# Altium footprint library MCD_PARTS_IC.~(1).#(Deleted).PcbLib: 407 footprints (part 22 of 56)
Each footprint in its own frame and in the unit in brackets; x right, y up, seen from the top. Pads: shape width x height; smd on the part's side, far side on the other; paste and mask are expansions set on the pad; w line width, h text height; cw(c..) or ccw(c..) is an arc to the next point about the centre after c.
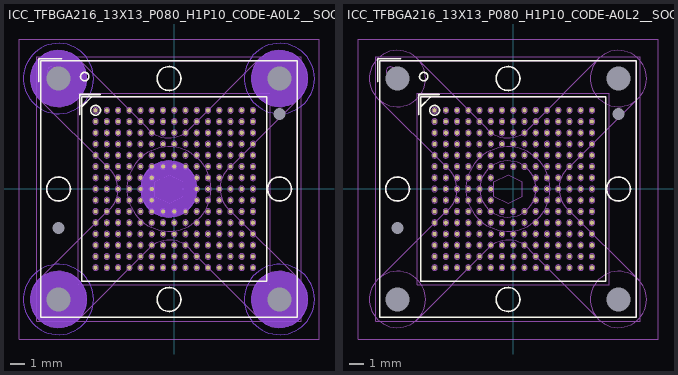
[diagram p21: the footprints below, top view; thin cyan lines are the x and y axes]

## ICC_TFBGA216_13X13_P080_H1P10_CODE-A0L2__SOCKET_IRONWOOD_CS1222291-D6524MF [mm] "MCD-02209"
height 8.25
pads (222):
  round 0.3 smd mask+0.05: A1(-5.6,5.6) A2(-4.8,5.6) A3(-4,5.6) A4(-3.2,5.6) A5(-2.4,5.6) A6(-1.6,5.6) A7(-0.8,5.6) A8(0,5.6) A9(0.8,5.6) A10(1.6,5.6) A11(2.4,5.6) A12(3.2,5.6) A13(4,5.6) A14(4.8,5.6) A15(5.6,5.6) B1(-5.6,4.8) B2(-4.8,4.8) B3(-4,4.8) B4(-3.2,4.8) B5(-2.4,4.8) B6(-1.6,4.8) B7(-0.8,4.8) B8(0,4.8) B9(0.8,4.8) B10(1.6,4.8) B11(2.4,4.8) B12(3.2,4.8) B13(4,4.8) B14(4.8,4.8) B15(5.6,4.8) C1(-5.6,4) C2(-4.8,4) C3(-4,4) C4(-3.2,4) C5(-2.4,4) C6(-1.6,4) C7(-0.8,4) C8(0,4) C9(0.8,4) C10(1.6,4) C11(2.4,4) C12(3.2,4) C13(4,4) C14(4.8,4) C15(5.6,4) D1(-5.6,3.2) D2(-4.8,3.2) D3(-4,3.2) D4(-3.2,3.2) D5(-2.4,3.2) D6(-1.6,3.2) D7(-0.8,3.2) D8(0,3.2) D9(0.8,3.2) D10(1.6,3.2) D11(2.4,3.2) D12(3.2,3.2) D13(4,3.2) D14(4.8,3.2) D15(5.6,3.2) E1(-5.6,2.4) E2(-4.8,2.4) E3(-4,2.4) E4(-3.2,2.4) E5(-2.4,2.4) E6(-1.6,2.4) E7(-0.8,2.4) E8(0,2.4) E9(0.8,2.4) E10(1.6,2.4) E11(2.4,2.4) E12(3.2,2.4) E13(4,2.4) E14(4.8,2.4) E15(5.6,2.4) F1(-5.6,1.6) F2(-4.8,1.6) F3(-4,1.6) F4(-3.2,1.6) F5(-2.4,1.6) F6(-1.6,1.6) F7(-0.8,1.6) F8(0,1.6) F9(0.8,1.6) F10(1.6,1.6) F11(2.4,1.6) F12(3.2,1.6) F13(4,1.6) F14(4.8,1.6) F15(5.6,1.6) G1(-5.6,0.8) G2(-4.8,0.8) G3(-4,0.8) G4(-3.2,0.8) G5(-2.4,0.8) G6(-1.6,0.8) G10(1.6,0.8) G11(2.4,0.8) G12(3.2,0.8) G13(4,0.8) G14(4.8,0.8) G15(5.6,0.8) H1(-5.6,0) H2(-4.8,0) H3(-4,0) H4(-3.2,0) H5(-2.4,0) H6(-1.6,0) H10(1.6,0) H11(2.4,0) H12(3.2,0) H13(4,0) H14(4.8,0) H15(5.6,0) J1(-5.6,-0.8) J2(-4.8,-0.8) J3(-4,-0.8) J4(-3.2,-0.8) J5(-2.4,-0.8) J6(-1.6,-0.8) J10(1.6,-0.8) J11(2.4,-0.8) J12(3.2,-0.8) J13(4,-0.8) J14(4.8,-0.8) J15(5.6,-0.8) K1(-5.6,-1.6) K2(-4.8,-1.6) K3(-4,-1.6) K4(-3.2,-1.6) K5(-2.4,-1.6) K6(-1.6,-1.6) K7(-0.8,-1.6) K8(0,-1.6) K9(0.8,-1.6) K10(1.6,-1.6) K11(2.4,-1.6) K12(3.2,-1.6) K13(4,-1.6) K14(4.8,-1.6) K15(5.6,-1.6) L1(-5.6,-2.4) L2(-4.8,-2.4) L3(-4,-2.4) L4(-3.2,-2.4) L5(-2.4,-2.4) L6(-1.6,-2.4) L7(-0.8,-2.4) L8(0,-2.4) L9(0.8,-2.4) L10(1.6,-2.4) L11(2.4,-2.4) L12(3.2,-2.4) L13(4,-2.4) L14(4.8,-2.4) L15(5.6,-2.4) M1(-5.6,-3.2) M2(-4.8,-3.2) M3(-4,-3.2) M4(-3.2,-3.2) M5(-2.4,-3.2) M6(-1.6,-3.2) M7(-0.8,-3.2) M8(0,-3.2) M9(0.8,-3.2) M10(1.6,-3.2) M11(2.4,-3.2) M12(3.2,-3.2) M13(4,-3.2) M14(4.8,-3.2) M15(5.6,-3.2) N1(-5.6,-4) N2(-4.8,-4) N3(-4,-4) N4(-3.2,-4) N5(-2.4,-4) N6(-1.6,-4) N7(-0.8,-4) N8(0,-4) N9(0.8,-4) N10(1.6,-4) N11(2.4,-4) N12(3.2,-4) N13(4,-4) N14(4.8,-4) N15(5.6,-4) P1(-5.6,-4.8) P2(-4.8,-4.8) P3(-4,-4.8) P4(-3.2,-4.8) P5(-2.4,-4.8) P6(-1.6,-4.8) P7(-0.8,-4.8) P8(0,-4.8) P9(0.8,-4.8) P10(1.6,-4.8) P11(2.4,-4.8) P12(3.2,-4.8) P13(4,-4.8) P14(4.8,-4.8) P15(5.6,-4.8) R1(-5.6,-5.6) R2(-4.8,-5.6) R3(-4,-5.6) R4(-3.2,-5.6) R5(-2.4,-5.6) R6(-1.6,-5.6) R7(-0.8,-5.6) R8(0,-5.6) R9(0.8,-5.6) R10(1.6,-5.6) R11(2.4,-5.6) R12(3.2,-5.6) R13(4,-5.6) R14(4.8,-5.6) R15(5.6,-5.6)
  round 0 hole 0.85 unplated mask+0.05: NPTH1(7.487,5.322) NPTH2(-8.238,-2.783)
  round 0 hole 1.71 unplated mask+0.05: PTH1(-8.238,7.862) PTH2(7.487,7.862) PTH3(7.487,-7.863) PTH4(-8.238,-7.863)
Bottom Layer keep-out:
  circle w0.01: c7.487,-7.863 r2.5
  circle w0.01: c-8.238,-7.863 r2.5
  circle w0.01: c-8.238,7.862 r2.5
  circle w0.01: c7.487,7.862 r2.5
  region: 1.6,-0.025 1.6,-0.221 1.524,-0.605 1.374,-0.966 1.156,-1.292 0.879,-1.569 0.554,-1.786 0.192,-1.936 -0.192,-2.012 -0.388,-2.012 -0.585,-2.012 -0.971,-1.936 -1.335,-1.785 -1.662,-1.566 -1.941,-1.287 -2.16,-0.96 -2.311,-0.596 -2.388,-0.209 -2.388,-0.012 -2.388,0.013 -2.388,0.209 -2.311,0.596 -2.16,0.96 -1.941,1.287 -1.662,1.566 -1.335,1.785 -0.971,1.936 -0.585,2.013 -0.388,2.013 -0.192,2.013 0.192,1.936 0.554,1.786 0.879,1.569 1.156,1.292 1.374,0.966 1.524,0.605 1.6,0.221 1.6,0.025
  region: -6.238,-7.888 -6.238,-8.083 -6.314,-8.467 -6.464,-8.829 -6.681,-9.154 -6.958,-9.431 -7.284,-9.649 -7.645,-9.799 -8.029,-9.875 -8.225,-9.875 -8.422,-9.875 -8.808,-9.798 -9.172,-9.647 -9.5,-9.429 -9.779,-9.15 -9.997,-8.822 -10.148,-8.458 -10.225,-8.072 -10.225,-7.875 -10.225,-7.85 -10.225,-7.653 -10.148,-7.267 -9.997,-6.903 -9.779,-6.575 -9.5,-6.296 -9.172,-6.078 -8.808,-5.927 -8.422,-5.85 -8.225,-5.85 -8.029,-5.85 -7.645,-5.926 -7.284,-6.076 -6.958,-6.294 -6.681,-6.571 -6.464,-6.896 -6.314,-7.258 -6.238,-7.642 -6.238,-7.838
  region: 9.487,-7.888 9.487,-8.083 9.411,-8.467 9.261,-8.829 9.044,-9.154 8.767,-9.431 8.441,-9.649 8.08,-9.799 7.696,-9.875 7.5,-9.875 7.303,-9.875 6.917,-9.798 6.553,-9.647 6.225,-9.429 5.946,-9.15 5.728,-8.822 5.577,-8.458 5.5,-8.072 5.5,-7.875 5.5,-7.85 5.5,-7.653 5.577,-7.267 5.728,-6.903 5.946,-6.575 6.225,-6.296 6.553,-6.078 6.917,-5.927 7.303,-5.85 7.5,-5.85 7.696,-5.85 8.08,-5.926 8.441,-6.076 8.767,-6.294 9.044,-6.571 9.261,-6.896 9.411,-7.258 9.487,-7.642 9.487,-7.838
  region: 9.487,7.838 9.487,7.642 9.411,7.258 9.261,6.896 9.044,6.571 8.767,6.294 8.441,6.076 8.08,5.926 7.696,5.85 7.5,5.85 7.303,5.85 6.917,5.927 6.553,6.078 6.225,6.296 5.946,6.575 5.728,6.903 5.577,7.267 5.5,7.653 5.5,7.85 5.5,7.875 5.5,8.072 5.577,8.458 5.728,8.822 5.946,9.15 6.225,9.429 6.553,9.647 6.917,9.798 7.303,9.875 7.5,9.875 7.696,9.875 8.08,9.799 8.441,9.649 8.767,9.431 9.044,9.154 9.261,8.829 9.411,8.467 9.487,8.083 9.487,7.888
  region: -6.238,7.838 -6.238,7.642 -6.314,7.258 -6.464,6.896 -6.681,6.571 -6.958,6.294 -7.284,6.076 -7.645,5.926 -8.029,5.85 -8.225,5.85 -8.422,5.85 -8.808,5.927 -9.172,6.078 -9.5,6.296 -9.779,6.575 -9.997,6.903 -10.148,7.267 -10.225,7.653 -10.225,7.85 -10.225,7.875 -10.225,8.072 -10.148,8.458 -9.997,8.822 -9.779,9.15 -9.5,9.429 -9.172,9.647 -8.808,9.798 -8.422,9.875 -8.225,9.875 -8.029,9.875 -7.645,9.799 -7.284,9.649 -6.958,9.431 -6.681,9.154 -6.464,8.829 -6.314,8.467 -6.238,8.083 -6.238,7.888
Top Overlay:
  circle w0.12: c-5.6,5.6 r0.35
  circle w0.12: c-8.238,0 r0.85
  circle w0.12: c-0.375,7.862 r0.85
  circle w0.12: c7.487,0 r0.85
  circle w0.12: c-0.375,-7.863 r0.85
  circle w0.12: c-6.375,8 r0.3
  lines w0.12: -9.65,7.625 -9.65,9.275 -8,9.275 ; -6.725,5.275 -6.725,6.725 -5.275,6.725 ; -6.55,5.895 -5.895,6.55 ; -9.5,-9.125 -9.5,9.125 8.75,9.125 8.75,-9.125 -9.5,-9.125 ; -6.575,-6.575 6.575,-6.575 6.575,6.575 -6.575,6.575 -6.575,-6.575
Bottom Overlay:
  lines w0.12: -10.75,-10.375 -10.75,10.375 -7.625,10.375 10,10.375 10,-10.375 -10.75,-10.375
M8-Bottom Info:
  circle w0.01: c-0.375,0 r2
  circle w0.01: c-8.238,7.862 r2
  circle w0.01: c7.487,7.862 r2
  circle w0.01: c7.487,-7.863 r2
  circle w0.01: c-8.238,-7.863 r2
  lines w0.01: -9.744,6.544 -4.624,1.424 ; -9.494,-6.319 -4.7,-1.525 ; -6.919,-9.369 -1.799,-4.249 ; -6.694,9.119 -1.9,4.325 ; -4.695,-1.531 ccw(c-6.015,-0.015) -4.618,1.43 ; -1.906,4.32 ccw(c-0.39,5.64) 1.055,4.243 ; -1.805,-4.243 cw(c-0.36,-5.64) 1.156,-4.32 ; 1.049,4.249 6.169,9.369 ; 1.15,-4.325 5.944,-9.119 ; 3.868,-1.43 cw(c5.265,0.015) 3.945,1.531 ; 3.874,-1.424 8.994,-6.544 ; 3.95,1.525 8.744,6.319
  text "Max Height :" at -3.725,2.15 h1.5
  text "1.4mm" at -2.05,-3.25 h1.5
M14-Top Assembly:
  drawing of 236 lines, arcs and shapes, not listed
  text "'.Designator'" at 0,0 h0.75
  text "A1" at -5.85,5.425 h0.4
M15-Bottom Assembly:
  circle w0.01: c-8.238,-7.863 r2
  circle w0.01: c7.487,-7.863 r2
  circle w0.01: c7.487,7.862 r2
  circle w0.01: c-8.238,7.862 r2
  circle w0.01: c-0.375,0 r2
  lines w0.01: -9.744,6.544 -4.624,1.424 ; -9.494,-6.319 -4.7,-1.525 ; -6.919,-9.369 -1.799,-4.249 ; -6.694,9.119 -1.9,4.325 ; -4.695,-1.531 ccw(c-6.015,-0.015) -4.618,1.43 ; -1.906,4.32 ccw(c-0.39,5.64) 1.055,4.243 ; -1.805,-4.243 cw(c-0.36,-5.64) 1.156,-4.32 ; 1.049,4.249 6.169,9.369 ; 1.15,-4.325 5.944,-9.119 ; 3.868,-1.43 cw(c5.265,0.015) 3.945,1.531 ; 3.874,-1.424 8.994,-6.544 ; 3.95,1.525 8.744,6.319
M16-Top Courtyard:
  lines w0.01: -9.8,-9.425 9.05,-9.425 9.05,9.425 -9.8,9.425 -9.8,8.5 -9.8,-9.425 ; -6.825,-6.825 6.825,-6.825 6.825,6.825 -6.825,6.825 -6.825,-6.825
M17-Bottom Courtyard:
  lines w0.01: -11.05,-10.675 -11.05,10.675 10.3,10.675 10.3,-10.675 -11.05,-10.675
3D body: height 0.36, standoff -0.04, extent 5.401,5.403 5.8,5.797
3D body: height 1.1, standoff 0.3, extent -6.55,-6.55 6.55,6.55
3D body: height 0.36, standoff -0.04, extent 4.601,5.403 5,5.797
3D body: height 0.36, standoff -0.04, extent 3.801,5.403 4.2,5.797
3D body: height 0.36, standoff -0.04, extent 3.001,5.403 3.4,5.797
3D body: height 0.36, standoff -0.04, extent 2.201,5.403 2.6,5.797
3D body: height 0.36, standoff -0.04, extent -1.799,5.403 -1.4,5.797
3D body: height 0.36, standoff -0.04, extent -0.999,5.403 -0.6,5.797
3D body: height 0.36, standoff -0.04, extent -0.199,5.403 0.2,5.797
3D body: height 0.36, standoff -0.04, extent 0.601,5.403 1,5.797
3D body: height 0.36, standoff -0.04, extent 1.401,5.403 1.8,5.797
3D body: height 0.36, standoff -0.04, extent -5.799,5.403 -5.4,5.797
3D body: height 0.36, standoff -0.04, extent -4.999,5.403 -4.6,5.797
3D body: height 0.36, standoff -0.04, extent -4.199,5.403 -3.8,5.797
3D body: height 0.36, standoff -0.04, extent -3.399,5.403 -3,5.797
3D body: height 0.36, standoff -0.04, extent -2.599,5.403 -2.2,5.797
3D body: height 0.36, standoff -0.04, extent -2.599,4.603 -2.2,4.997
3D body: height 0.36, standoff -0.04, extent -3.399,4.603 -3,4.997
3D body: height 0.36, standoff -0.04, extent -4.199,4.603 -3.8,4.997
3D body: height 0.36, standoff -0.04, extent -4.999,4.603 -4.6,4.997
3D body: height 0.36, standoff -0.04, extent -5.799,4.603 -5.4,4.997
3D body: height 0.36, standoff -0.04, extent 1.401,4.603 1.8,4.997
3D body: height 0.36, standoff -0.04, extent 0.601,4.603 1,4.997
3D body: height 0.36, standoff -0.04, extent -0.199,4.603 0.2,4.997
3D body: height 0.36, standoff -0.04, extent -0.999,4.603 -0.6,4.997
3D body: height 0.36, standoff -0.04, extent -1.799,4.603 -1.4,4.997
3D body: height 0.36, standoff -0.04, extent 2.201,4.603 2.6,4.997
3D body: height 0.36, standoff -0.04, extent 3.001,4.603 3.4,4.997
3D body: height 0.36, standoff -0.04, extent 3.801,4.603 4.2,4.997
3D body: height 0.36, standoff -0.04, extent 4.601,4.603 5,4.997
3D body: height 0.36, standoff -0.04, extent 5.401,4.603 5.8,4.997
3D body: height 0.36, standoff -0.04, extent -2.599,3.803 -2.2,4.197
3D body: height 0.36, standoff -0.04, extent -3.399,3.803 -3,4.197
3D body: height 0.36, standoff -0.04, extent -4.199,3.803 -3.8,4.197
3D body: height 0.36, standoff -0.04, extent -4.999,3.803 -4.6,4.197
3D body: height 0.36, standoff -0.04, extent -5.799,3.803 -5.4,4.197
3D body: height 0.36, standoff -0.04, extent 1.401,3.803 1.8,4.197
3D body: height 0.36, standoff -0.04, extent 0.601,3.803 1,4.197
3D body: height 0.36, standoff -0.04, extent -0.199,3.803 0.2,4.197
3D body: height 0.36, standoff -0.04, extent -0.999,3.803 -0.6,4.197
3D body: height 0.36, standoff -0.04, extent -1.799,3.803 -1.4,4.197
3D body: height 0.36, standoff -0.04, extent 2.201,3.803 2.6,4.197
3D body: height 0.36, standoff -0.04, extent 3.001,3.803 3.4,4.197
3D body: height 0.36, standoff -0.04, extent 3.801,3.803 4.2,4.197
3D body: height 0.36, standoff -0.04, extent 4.601,3.803 5,4.197
3D body: height 0.36, standoff -0.04, extent 5.401,3.803 5.8,4.197
3D body: height 0.36, standoff -0.04, extent -2.599,3.003 -2.2,3.397
3D body: height 0.36, standoff -0.04, extent -3.399,3.003 -3,3.397
3D body: height 0.36, standoff -0.04, extent -4.199,3.003 -3.8,3.397
3D body: height 0.36, standoff -0.04, extent -4.999,3.003 -4.6,3.397
3D body: height 0.36, standoff -0.04, extent -5.799,3.003 -5.4,3.397
3D body: height 0.36, standoff -0.04, extent 1.401,3.003 1.8,3.397
3D body: height 0.36, standoff -0.04, extent 0.601,3.003 1,3.397
3D body: height 0.36, standoff -0.04, extent -0.199,3.003 0.2,3.397
3D body: height 0.36, standoff -0.04, extent -0.999,3.003 -0.6,3.397
3D body: height 0.36, standoff -0.04, extent -1.799,3.003 -1.4,3.397
3D body: height 0.36, standoff -0.04, extent 2.201,3.003 2.6,3.397
3D body: height 0.36, standoff -0.04, extent 3.001,3.003 3.4,3.397
3D body: height 0.36, standoff -0.04, extent 3.801,3.003 4.2,3.397
3D body: height 0.36, standoff -0.04, extent 4.601,3.003 5,3.397
3D body: height 0.36, standoff -0.04, extent 5.401,3.003 5.8,3.397
3D body: height 0.36, standoff -0.04, extent -2.599,2.203 -2.2,2.597
3D body: height 0.36, standoff -0.04, extent -3.399,2.203 -3,2.597
3D body: height 0.36, standoff -0.04, extent -4.199,2.203 -3.8,2.597
3D body: height 0.36, standoff -0.04, extent -4.999,2.203 -4.6,2.597
3D body: height 0.36, standoff -0.04, extent -5.799,2.203 -5.4,2.597
3D body: height 0.36, standoff -0.04, extent 1.401,2.203 1.8,2.597
3D body: height 0.36, standoff -0.04, extent 0.601,2.203 1,2.597
3D body: height 0.36, standoff -0.04, extent -0.199,2.203 0.2,2.597
3D body: height 0.36, standoff -0.04, extent -0.999,2.203 -0.6,2.597
3D body: height 0.36, standoff -0.04, extent -1.799,2.203 -1.4,2.597
3D body: height 0.36, standoff -0.04, extent 2.201,2.203 2.6,2.597
3D body: height 0.36, standoff -0.04, extent 3.001,2.203 3.4,2.597
3D body: height 0.36, standoff -0.04, extent 3.801,2.203 4.2,2.597
3D body: height 0.36, standoff -0.04, extent 4.601,2.203 5,2.597
3D body: height 0.36, standoff -0.04, extent 5.401,2.203 5.8,2.597
3D body: height 0.36, standoff -0.04, extent -2.599,1.403 -2.2,1.797
3D body: height 0.36, standoff -0.04, extent -3.399,1.403 -3,1.797
3D body: height 0.36, standoff -0.04, extent -4.199,1.403 -3.8,1.797
3D body: height 0.36, standoff -0.04, extent -4.999,1.403 -4.6,1.797
3D body: height 0.36, standoff -0.04, extent -5.799,1.403 -5.4,1.797
3D body: height 0.36, standoff -0.04, extent 1.401,1.403 1.8,1.797
3D body: height 0.36, standoff -0.04, extent 0.601,1.403 1,1.797
3D body: height 0.36, standoff -0.04, extent -0.199,1.403 0.2,1.797
3D body: height 0.36, standoff -0.04, extent -0.999,1.403 -0.6,1.797
3D body: height 0.36, standoff -0.04, extent -1.799,1.403 -1.4,1.797
3D body: height 0.36, standoff -0.04, extent 2.201,1.403 2.6,1.797
3D body: height 0.36, standoff -0.04, extent 3.001,1.403 3.4,1.797
3D body: height 0.36, standoff -0.04, extent 3.801,1.403 4.2,1.797
3D body: height 0.36, standoff -0.04, extent 4.601,1.403 5,1.797
3D body: height 0.36, standoff -0.04, extent 5.401,1.403 5.8,1.797
3D body: height 0.36, standoff -0.04, extent -2.599,0.603 -2.2,0.997
3D body: height 0.36, standoff -0.04, extent -3.399,0.603 -3,0.997
3D body: height 0.36, standoff -0.04, extent -4.199,0.603 -3.8,0.997
3D body: height 0.36, standoff -0.04, extent -4.999,0.603 -4.6,0.997
3D body: height 0.36, standoff -0.04, extent -5.799,0.603 -5.4,0.997
3D body: height 0.36, standoff -0.04, extent 1.401,0.603 1.8,0.997
3D body: height 0.36, standoff -0.04, extent -1.799,0.603 -1.4,0.997
3D body: height 0.36, standoff -0.04, extent 2.201,0.603 2.6,0.997
3D body: height 0.36, standoff -0.04, extent 3.001,0.603 3.4,0.997
3D body: height 0.36, standoff -0.04, extent 3.801,0.603 4.2,0.997
3D body: height 0.36, standoff -0.04, extent 4.601,0.603 5,0.997
3D body: height 0.36, standoff -0.04, extent 5.401,0.603 5.8,0.997
3D body: height 0.36, standoff -0.04, extent -2.599,-0.197 -2.2,0.197
3D body: height 0.36, standoff -0.04, extent -3.399,-0.197 -3,0.197
3D body: height 0.36, standoff -0.04, extent -4.199,-0.197 -3.8,0.197
3D body: height 0.36, standoff -0.04, extent -4.999,-0.197 -4.6,0.197
3D body: height 0.36, standoff -0.04, extent -5.799,-0.197 -5.4,0.197
3D body: height 0.36, standoff -0.04, extent 1.401,-0.197 1.8,0.197
3D body: height 0.36, standoff -0.04, extent -1.799,-0.197 -1.4,0.197
3D body: height 0.36, standoff -0.04, extent 2.201,-0.197 2.6,0.197
3D body: height 0.36, standoff -0.04, extent 3.001,-0.197 3.4,0.197
3D body: height 0.36, standoff -0.04, extent 3.801,-0.197 4.2,0.197
3D body: height 0.36, standoff -0.04, extent 4.601,-0.197 5,0.197
3D body: height 0.36, standoff -0.04, extent 5.401,-0.197 5.8,0.197
3D body: height 0.36, standoff -0.04, extent -2.599,-0.997 -2.2,-0.603
3D body: height 0.36, standoff -0.04, extent -3.399,-0.997 -3,-0.603
3D body: height 0.36, standoff -0.04, extent -4.199,-0.997 -3.8,-0.603
3D body: height 0.36, standoff -0.04, extent -4.999,-0.997 -4.6,-0.603
3D body: height 0.36, standoff -0.04, extent -5.799,-0.997 -5.4,-0.603
3D body: height 0.36, standoff -0.04, extent 1.401,-0.997 1.8,-0.603
3D body: height 0.36, standoff -0.04, extent -1.799,-0.997 -1.4,-0.603
3D body: height 0.36, standoff -0.04, extent 2.201,-0.997 2.6,-0.603
3D body: height 0.36, standoff -0.04, extent 3.001,-0.997 3.4,-0.603
3D body: height 0.36, standoff -0.04, extent 3.801,-0.997 4.2,-0.603
3D body: height 0.36, standoff -0.04, extent 4.601,-0.997 5,-0.603
3D body: height 0.36, standoff -0.04, extent 5.401,-0.997 5.8,-0.603
3D body: height 0.36, standoff -0.04, extent -2.599,-1.797 -2.2,-1.403
3D body: height 0.36, standoff -0.04, extent -3.399,-1.797 -3,-1.403
3D body: height 0.36, standoff -0.04, extent -4.199,-1.797 -3.8,-1.403
3D body: height 0.36, standoff -0.04, extent -4.999,-1.797 -4.6,-1.403
3D body: height 0.36, standoff -0.04, extent -5.799,-1.797 -5.4,-1.403
3D body: height 0.36, standoff -0.04, extent 1.401,-1.797 1.8,-1.403
3D body: height 0.36, standoff -0.04, extent 0.601,-1.797 1,-1.403
3D body: height 0.36, standoff -0.04, extent -0.199,-1.797 0.2,-1.403
3D body: height 0.36, standoff -0.04, extent -0.999,-1.797 -0.6,-1.403
3D body: height 0.36, standoff -0.04, extent -1.799,-1.797 -1.4,-1.403
3D body: height 0.36, standoff -0.04, extent 2.201,-1.797 2.6,-1.403
3D body: height 0.36, standoff -0.04, extent 3.001,-1.797 3.4,-1.403
3D body: height 0.36, standoff -0.04, extent 3.801,-1.797 4.2,-1.403
3D body: height 0.36, standoff -0.04, extent 4.601,-1.797 5,-1.403
3D body: height 0.36, standoff -0.04, extent 5.401,-1.797 5.8,-1.403
3D body: height 0.36, standoff -0.04, extent -2.599,-2.597 -2.2,-2.203
3D body: height 0.36, standoff -0.04, extent -3.399,-2.597 -3,-2.203
3D body: height 0.36, standoff -0.04, extent -4.199,-2.597 -3.8,-2.203
3D body: height 0.36, standoff -0.04, extent -4.999,-2.597 -4.6,-2.203
3D body: height 0.36, standoff -0.04, extent -5.799,-2.597 -5.4,-2.203
3D body: height 0.36, standoff -0.04, extent 1.401,-2.597 1.8,-2.203
3D body: height 0.36, standoff -0.04, extent 0.601,-2.597 1,-2.203
3D body: height 0.36, standoff -0.04, extent -0.199,-2.597 0.2,-2.203
3D body: height 0.36, standoff -0.04, extent -0.999,-2.597 -0.6,-2.203
3D body: height 0.36, standoff -0.04, extent -1.799,-2.597 -1.4,-2.203
3D body: height 0.36, standoff -0.04, extent 2.201,-2.597 2.6,-2.203
3D body: height 0.36, standoff -0.04, extent 3.001,-2.597 3.4,-2.203
3D body: height 0.36, standoff -0.04, extent 3.801,-2.597 4.2,-2.203
3D body: height 0.36, standoff -0.04, extent 4.601,-2.597 5,-2.203
3D body: height 0.36, standoff -0.04, extent 5.401,-2.597 5.8,-2.203
3D body: height 0.36, standoff -0.04, extent -2.599,-3.397 -2.2,-3.003
3D body: height 0.36, standoff -0.04, extent -3.399,-3.397 -3,-3.003
3D body: height 0.36, standoff -0.04, extent -4.199,-3.397 -3.8,-3.003
3D body: height 0.36, standoff -0.04, extent -4.999,-3.397 -4.6,-3.003
3D body: height 0.36, standoff -0.04, extent -5.799,-3.397 -5.4,-3.003
3D body: height 0.36, standoff -0.04, extent 1.401,-3.397 1.8,-3.003
3D body: height 0.36, standoff -0.04, extent 0.601,-3.397 1,-3.003
3D body: height 0.36, standoff -0.04, extent -0.199,-3.397 0.2,-3.003
3D body: height 0.36, standoff -0.04, extent -0.999,-3.397 -0.6,-3.003
3D body: height 0.36, standoff -0.04, extent -1.799,-3.397 -1.4,-3.003
3D body: height 0.36, standoff -0.04, extent 2.201,-3.397 2.6,-3.003
3D body: height 0.36, standoff -0.04, extent 3.001,-3.397 3.4,-3.003
3D body: height 0.36, standoff -0.04, extent 3.801,-3.397 4.2,-3.003
3D body: height 0.36, standoff -0.04, extent 4.601,-3.397 5,-3.003
3D body: height 0.36, standoff -0.04, extent 5.401,-3.397 5.8,-3.003
3D body: height 0.36, standoff -0.04, extent -2.599,-4.197 -2.2,-3.803
3D body: height 0.36, standoff -0.04, extent -3.399,-4.197 -3,-3.803
3D body: height 0.36, standoff -0.04, extent -4.199,-4.197 -3.8,-3.803
3D body: height 0.36, standoff -0.04, extent -4.999,-4.197 -4.6,-3.803
3D body: height 0.36, standoff -0.04, extent -5.799,-4.197 -5.4,-3.803
3D body: height 0.36, standoff -0.04, extent 1.401,-4.197 1.8,-3.803
3D body: height 0.36, standoff -0.04, extent 0.601,-4.197 1,-3.803
3D body: height 0.36, standoff -0.04, extent -0.199,-4.197 0.2,-3.803
3D body: height 0.36, standoff -0.04, extent -0.999,-4.197 -0.6,-3.803
3D body: height 0.36, standoff -0.04, extent -1.799,-4.197 -1.4,-3.803
3D body: height 0.36, standoff -0.04, extent 2.201,-4.197 2.6,-3.803
3D body: height 0.36, standoff -0.04, extent 3.001,-4.197 3.4,-3.803
3D body: height 0.36, standoff -0.04, extent 3.801,-4.197 4.2,-3.803
3D body: height 0.36, standoff -0.04, extent 4.601,-4.197 5,-3.803
3D body: height 0.36, standoff -0.04, extent 5.401,-4.197 5.8,-3.803
3D body: height 0.36, standoff -0.04, extent -2.599,-4.997 -2.2,-4.603
3D body: height 0.36, standoff -0.04, extent -3.399,-4.997 -3,-4.603
3D body: height 0.36, standoff -0.04, extent -4.199,-4.997 -3.8,-4.603
3D body: height 0.36, standoff -0.04, extent -4.999,-4.997 -4.6,-4.603
3D body: height 0.36, standoff -0.04, extent -5.799,-4.997 -5.4,-4.603
3D body: height 0.36, standoff -0.04, extent 1.401,-4.997 1.8,-4.603
3D body: height 0.36, standoff -0.04, extent 0.601,-4.997 1,-4.603
3D body: height 0.36, standoff -0.04, extent -0.199,-4.997 0.2,-4.603
3D body: height 0.36, standoff -0.04, extent -0.999,-4.997 -0.6,-4.603
3D body: height 0.36, standoff -0.04, extent -1.799,-4.997 -1.4,-4.603
3D body: height 0.36, standoff -0.04, extent 2.201,-4.997 2.6,-4.603
3D body: height 0.36, standoff -0.04, extent 3.001,-4.997 3.4,-4.603
3D body: height 0.36, standoff -0.04, extent 3.801,-4.997 4.2,-4.603
3D body: height 0.36, standoff -0.04, extent 4.601,-4.997 5,-4.603
3D body: height 0.36, standoff -0.04, extent 5.401,-4.997 5.8,-4.603
3D body: height 0.36, standoff -0.04, extent -2.599,-5.797 -2.2,-5.403
3D body: height 0.36, standoff -0.04, extent -3.399,-5.797 -3,-5.403
3D body: height 0.36, standoff -0.04, extent -4.199,-5.797 -3.8,-5.403
3D body: height 0.36, standoff -0.04, extent -4.999,-5.797 -4.6,-5.403
3D body: height 0.36, standoff -0.04, extent -5.799,-5.797 -5.4,-5.403
3D body: height 0.36, standoff -0.04, extent 1.401,-5.797 1.8,-5.403
3D body: height 0.36, standoff -0.04, extent 0.601,-5.797 1,-5.403
3D body: height 0.36, standoff -0.04, extent -0.199,-5.797 0.2,-5.403
3D body: height 0.36, standoff -0.04, extent -0.999,-5.797 -0.6,-5.403
3D body: height 0.36, standoff -0.04, extent -1.799,-5.797 -1.4,-5.403
3D body: height 0.36, standoff -0.04, extent 2.201,-5.797 2.6,-5.403
3D body: height 0.36, standoff -0.04, extent 3.001,-5.797 3.4,-5.403
3D body: height 0.36, standoff -0.04, extent 3.801,-5.797 4.2,-5.403
3D body: height 0.36, standoff -0.04, extent 4.601,-5.797 5,-5.403
3D body: height 0.36, standoff -0.04, extent 5.401,-5.797 5.8,-5.403
3D body: height 1.11, standoff 1.1, extent -5.898,5.301 -5.3,5.9
3D body: height 8.26, standoff 8.25, extent -1.375,-1 0.625,1
3D body: height 5, standoff 0, extent -9.488,-9.113 8.737,9.112
3D body: height 8.25, standoff 5, extent -3.375,-3 2.625,3
3D body: height 6, standoff 5, extent -1.218,-8.711 0.475,-7.014
3D body: height 6, standoff 5, extent 6.644,-0.848 8.338,0.848
3D body: height 6, standoff 5, extent -1.218,7.014 0.475,8.711
3D body: height 6, standoff 5, extent -9.081,-0.848 -7.387,0.848
3D body "M5398MF.STEP": height -1.7, standoff -5.7, extent -10.262,-9.862 9.463,9.863

## ICC_TFBGA216_13X13_P080_H1P10_CODE-A0L2__SOCKET_IRONWOOD_CS1222291-D6524MF - duplicate [mm] "MCD-02209"
height 8.25
pads (222):
  round 0.3 smd mask+0.05: A1(-5.6,5.6) A2(-4.8,5.6) A3(-4,5.6) A4(-3.2,5.6) A5(-2.4,5.6) A6(-1.6,5.6) A7(-0.8,5.6) A8(0,5.6) A9(0.8,5.6) A10(1.6,5.6) A11(2.4,5.6) A12(3.2,5.6) A13(4,5.6) A14(4.8,5.6) A15(5.6,5.6) B1(-5.6,4.8) B2(-4.8,4.8) B3(-4,4.8) B4(-3.2,4.8) B5(-2.4,4.8) B6(-1.6,4.8) B7(-0.8,4.8) B8(0,4.8) B9(0.8,4.8) B10(1.6,4.8) B11(2.4,4.8) B12(3.2,4.8) B13(4,4.8) B14(4.8,4.8) B15(5.6,4.8) C1(-5.6,4) C2(-4.8,4) C3(-4,4) C4(-3.2,4) C5(-2.4,4) C6(-1.6,4) C7(-0.8,4) C8(0,4) C9(0.8,4) C10(1.6,4) C11(2.4,4) C12(3.2,4) C13(4,4) C14(4.8,4) C15(5.6,4) D1(-5.6,3.2) D2(-4.8,3.2) D3(-4,3.2) D4(-3.2,3.2) D5(-2.4,3.2) D6(-1.6,3.2) D7(-0.8,3.2) D8(0,3.2) D9(0.8,3.2) D10(1.6,3.2) D11(2.4,3.2) D12(3.2,3.2) D13(4,3.2) D14(4.8,3.2) D15(5.6,3.2) E1(-5.6,2.4) E2(-4.8,2.4) E3(-4,2.4) E4(-3.2,2.4) E5(-2.4,2.4) E6(-1.6,2.4) E7(-0.8,2.4) E8(0,2.4) E9(0.8,2.4) E10(1.6,2.4) E11(2.4,2.4) E12(3.2,2.4) E13(4,2.4) E14(4.8,2.4) E15(5.6,2.4) F1(-5.6,1.6) F2(-4.8,1.6) F3(-4,1.6) F4(-3.2,1.6) F5(-2.4,1.6) F6(-1.6,1.6) F7(-0.8,1.6) F8(0,1.6) F9(0.8,1.6) F10(1.6,1.6) F11(2.4,1.6) F12(3.2,1.6) F13(4,1.6) F14(4.8,1.6) F15(5.6,1.6) G1(-5.6,0.8) G2(-4.8,0.8) G3(-4,0.8) G4(-3.2,0.8) G5(-2.4,0.8) G6(-1.6,0.8) G10(1.6,0.8) G11(2.4,0.8) G12(3.2,0.8) G13(4,0.8) G14(4.8,0.8) G15(5.6,0.8) H1(-5.6,0) H2(-4.8,0) H3(-4,0) H4(-3.2,0) H5(-2.4,0) H6(-1.6,0) H10(1.6,0) H11(2.4,0) H12(3.2,0) H13(4,0) H14(4.8,0) H15(5.6,0) J1(-5.6,-0.8) J2(-4.8,-0.8) J3(-4,-0.8) J4(-3.2,-0.8) J5(-2.4,-0.8) J6(-1.6,-0.8) J10(1.6,-0.8) J11(2.4,-0.8) J12(3.2,-0.8) J13(4,-0.8) J14(4.8,-0.8) J15(5.6,-0.8) K1(-5.6,-1.6) K2(-4.8,-1.6) K3(-4,-1.6) K4(-3.2,-1.6) K5(-2.4,-1.6) K6(-1.6,-1.6) K7(-0.8,-1.6) K8(0,-1.6) K9(0.8,-1.6) K10(1.6,-1.6) K11(2.4,-1.6) K12(3.2,-1.6) K13(4,-1.6) K14(4.8,-1.6) K15(5.6,-1.6) L1(-5.6,-2.4) L2(-4.8,-2.4) L3(-4,-2.4) L4(-3.2,-2.4) L5(-2.4,-2.4) L6(-1.6,-2.4) L7(-0.8,-2.4) L8(0,-2.4) L9(0.8,-2.4) L10(1.6,-2.4) L11(2.4,-2.4) L12(3.2,-2.4) L13(4,-2.4) L14(4.8,-2.4) L15(5.6,-2.4) M1(-5.6,-3.2) M2(-4.8,-3.2) M3(-4,-3.2) M4(-3.2,-3.2) M5(-2.4,-3.2) M6(-1.6,-3.2) M7(-0.8,-3.2) M8(0,-3.2) M9(0.8,-3.2) M10(1.6,-3.2) M11(2.4,-3.2) M12(3.2,-3.2) M13(4,-3.2) M14(4.8,-3.2) M15(5.6,-3.2) N1(-5.6,-4) N2(-4.8,-4) N3(-4,-4) N4(-3.2,-4) N5(-2.4,-4) N6(-1.6,-4) N7(-0.8,-4) N8(0,-4) N9(0.8,-4) N10(1.6,-4) N11(2.4,-4) N12(3.2,-4) N13(4,-4) N14(4.8,-4) N15(5.6,-4) P1(-5.6,-4.8) P2(-4.8,-4.8) P3(-4,-4.8) P4(-3.2,-4.8) P5(-2.4,-4.8) P6(-1.6,-4.8) P7(-0.8,-4.8) P8(0,-4.8) P9(0.8,-4.8) P10(1.6,-4.8) P11(2.4,-4.8) P12(3.2,-4.8) P13(4,-4.8) P14(4.8,-4.8) P15(5.6,-4.8) R1(-5.6,-5.6) R2(-4.8,-5.6) R3(-4,-5.6) R4(-3.2,-5.6) R5(-2.4,-5.6) R6(-1.6,-5.6) R7(-0.8,-5.6) R8(0,-5.6) R9(0.8,-5.6) R10(1.6,-5.6) R11(2.4,-5.6) R12(3.2,-5.6) R13(4,-5.6) R14(4.8,-5.6) R15(5.6,-5.6)
  round 0 hole 0.85 unplated mask+0.05: NPTH1(7.487,5.322) NPTH2(-8.238,-2.783)
  round 0 hole 1.71 unplated mask+0.05: PTH1(-8.238,7.862) PTH2(7.487,7.862) PTH3(7.487,-7.863) PTH4(-8.238,-7.863)
Top Overlay:
  circle w0.12: c-6.375,8 r0.3
  circle w0.12: c-0.375,-7.863 r0.85
  circle w0.12: c7.487,0 r0.85
  circle w0.12: c-0.375,7.862 r0.85
  circle w0.12: c-8.238,0 r0.85
  circle w0.12: c-5.6,5.6 r0.35
  lines w0.12: -9.65,7.625 -9.65,9.275 -8,9.275 ; -6.725,5.275 -6.725,6.725 -5.275,6.725 ; -6.55,5.895 -5.895,6.55 ; -9.5,-9.125 8.75,-9.125 8.75,9.125 -9.5,9.125 -9.5,-9.125 ; -6.575,-6.575 -6.575,6.575 6.575,6.575 6.575,-6.575 -6.575,-6.575
Bottom Overlay:
  lines w0.12: -10.75,-10.375 10,-10.375 10,10.375 -7.625,10.375 -10.75,10.375 -10.75,-10.375
M8-Bottom Info:
  circle w0.01: c-8.238,-7.863 r2
  circle w0.01: c7.487,-7.863 r2
  circle w0.01: c7.487,7.862 r2
  circle w0.01: c-8.238,7.862 r2
  circle w0.01: c-0.375,0 r2
  lines w0.01: -9.744,6.544 -4.624,1.424 ; -9.494,-6.319 -4.7,-1.525 ; -6.919,-9.369 -1.799,-4.249 ; -6.694,9.119 -1.9,4.325 ; -4.695,-1.531 ccw(c-6.015,-0.015) -4.618,1.43 ; -1.906,4.32 ccw(c-0.39,5.64) 1.055,4.243 ; -1.805,-4.243 cw(c-0.36,-5.64) 1.156,-4.32 ; 1.049,4.249 6.169,9.369 ; 1.15,-4.325 5.944,-9.119 ; 3.868,-1.43 cw(c5.265,0.015) 3.945,1.531 ; 3.874,-1.424 8.994,-6.544 ; 3.95,1.525 8.744,6.319
  text "1.4mm" at -2.05,-3.25 h1.5
  text "Max Height :" at -3.725,2.15 h1.5
M14-Top Assembly:
  drawing of 236 lines, arcs and shapes, not listed
  text "A1" at -5.85,5.425 h0.4
  text "'.Designator'" at 0,0 h0.75
M15-Bottom Assembly:
  circle w0.01: c-0.375,0 r2
  circle w0.01: c-8.238,7.862 r2
  circle w0.01: c7.487,7.862 r2
  circle w0.01: c7.487,-7.863 r2
  circle w0.01: c-8.238,-7.863 r2
  lines w0.01: -9.744,6.544 -4.624,1.424 ; -9.494,-6.319 -4.7,-1.525 ; -6.919,-9.369 -1.799,-4.249 ; -6.694,9.119 -1.9,4.325 ; -4.695,-1.531 ccw(c-6.015,-0.015) -4.618,1.43 ; -1.906,4.32 ccw(c-0.39,5.64) 1.055,4.243 ; -1.805,-4.243 cw(c-0.36,-5.64) 1.156,-4.32 ; 1.049,4.249 6.169,9.369 ; 1.15,-4.325 5.944,-9.119 ; 3.868,-1.43 cw(c5.265,0.015) 3.945,1.531 ; 3.874,-1.424 8.994,-6.544 ; 3.95,1.525 8.744,6.319
M16-Top Courtyard:
  lines w0.01: -9.8,-9.425 -9.8,8.5 -9.8,9.425 9.05,9.425 9.05,-9.425 -9.8,-9.425 ; -6.825,-6.825 -6.825,6.825 6.825,6.825 6.825,-6.825 -6.825,-6.825
M17-Bottom Courtyard:
  lines w0.01: -11.05,-10.675 10.3,-10.675 10.3,10.675 -11.05,10.675 -11.05,-10.675
3D body: height 6, standoff 5, extent -9.081,-0.848 -7.387,0.848
3D body: height 6, standoff 5, extent -1.218,7.014 0.475,8.711
3D body: height 6, standoff 5, extent 6.644,-0.848 8.338,0.848
3D body: height 6, standoff 5, extent -1.218,-8.711 0.475,-7.014
3D body: height 8.25, standoff 5, extent -3.375,-3 2.625,3
3D body: height 5, standoff 0, extent -9.488,-9.113 8.737,9.112
3D body: height 8.26, standoff 8.25, extent -1.375,-1 0.625,1
3D body: height 1.11, standoff 1.1, extent -5.898,5.301 -5.3,5.9
3D body: height 0.36, standoff -0.04, extent 5.401,-5.797 5.8,-5.403
3D body: height 0.36, standoff -0.04, extent 4.601,-5.797 5,-5.403
3D body: height 0.36, standoff -0.04, extent 3.801,-5.797 4.2,-5.403
3D body: height 0.36, standoff -0.04, extent 3.001,-5.797 3.4,-5.403
3D body: height 0.36, standoff -0.04, extent 2.201,-5.797 2.6,-5.403
3D body: height 0.36, standoff -0.04, extent -1.799,-5.797 -1.4,-5.403
3D body: height 0.36, standoff -0.04, extent -0.999,-5.797 -0.6,-5.403
3D body: height 0.36, standoff -0.04, extent -0.199,-5.797 0.2,-5.403
3D body: height 0.36, standoff -0.04, extent 0.601,-5.797 1,-5.403
3D body: height 0.36, standoff -0.04, extent 1.401,-5.797 1.8,-5.403
3D body: height 0.36, standoff -0.04, extent -5.799,-5.797 -5.4,-5.403
3D body: height 0.36, standoff -0.04, extent -4.999,-5.797 -4.6,-5.403
3D body: height 0.36, standoff -0.04, extent -4.199,-5.797 -3.8,-5.403
3D body: height 0.36, standoff -0.04, extent -3.399,-5.797 -3,-5.403
3D body: height 0.36, standoff -0.04, extent -2.599,-5.797 -2.2,-5.403
3D body: height 0.36, standoff -0.04, extent 5.401,-4.997 5.8,-4.603
3D body: height 0.36, standoff -0.04, extent 4.601,-4.997 5,-4.603
3D body: height 0.36, standoff -0.04, extent 3.801,-4.997 4.2,-4.603
3D body: height 0.36, standoff -0.04, extent 3.001,-4.997 3.4,-4.603
3D body: height 0.36, standoff -0.04, extent 2.201,-4.997 2.6,-4.603
3D body: height 0.36, standoff -0.04, extent -1.799,-4.997 -1.4,-4.603
3D body: height 0.36, standoff -0.04, extent -0.999,-4.997 -0.6,-4.603
3D body: height 0.36, standoff -0.04, extent -0.199,-4.997 0.2,-4.603
3D body: height 0.36, standoff -0.04, extent 0.601,-4.997 1,-4.603
3D body: height 0.36, standoff -0.04, extent 1.401,-4.997 1.8,-4.603
3D body: height 0.36, standoff -0.04, extent -5.799,-4.997 -5.4,-4.603
3D body: height 0.36, standoff -0.04, extent -4.999,-4.997 -4.6,-4.603
3D body: height 0.36, standoff -0.04, extent -4.199,-4.997 -3.8,-4.603
3D body: height 0.36, standoff -0.04, extent -3.399,-4.997 -3,-4.603
3D body: height 0.36, standoff -0.04, extent -2.599,-4.997 -2.2,-4.603
3D body: height 0.36, standoff -0.04, extent 5.401,-4.197 5.8,-3.803
3D body: height 0.36, standoff -0.04, extent 4.601,-4.197 5,-3.803
3D body: height 0.36, standoff -0.04, extent 3.801,-4.197 4.2,-3.803
3D body: height 0.36, standoff -0.04, extent 3.001,-4.197 3.4,-3.803
3D body: height 0.36, standoff -0.04, extent 2.201,-4.197 2.6,-3.803
3D body: height 0.36, standoff -0.04, extent -1.799,-4.197 -1.4,-3.803
3D body: height 0.36, standoff -0.04, extent -0.999,-4.197 -0.6,-3.803
3D body: height 0.36, standoff -0.04, extent -0.199,-4.197 0.2,-3.803
3D body: height 0.36, standoff -0.04, extent 0.601,-4.197 1,-3.803
3D body: height 0.36, standoff -0.04, extent 1.401,-4.197 1.8,-3.803
3D body: height 0.36, standoff -0.04, extent -5.799,-4.197 -5.4,-3.803
3D body: height 0.36, standoff -0.04, extent -4.999,-4.197 -4.6,-3.803
3D body: height 0.36, standoff -0.04, extent -4.199,-4.197 -3.8,-3.803
3D body: height 0.36, standoff -0.04, extent -3.399,-4.197 -3,-3.803
3D body: height 0.36, standoff -0.04, extent -2.599,-4.197 -2.2,-3.803
3D body: height 0.36, standoff -0.04, extent 5.401,-3.397 5.8,-3.003
3D body: height 0.36, standoff -0.04, extent 4.601,-3.397 5,-3.003
3D body: height 0.36, standoff -0.04, extent 3.801,-3.397 4.2,-3.003
3D body: height 0.36, standoff -0.04, extent 3.001,-3.397 3.4,-3.003
3D body: height 0.36, standoff -0.04, extent 2.201,-3.397 2.6,-3.003
3D body: height 0.36, standoff -0.04, extent -1.799,-3.397 -1.4,-3.003
3D body: height 0.36, standoff -0.04, extent -0.999,-3.397 -0.6,-3.003
3D body: height 0.36, standoff -0.04, extent -0.199,-3.397 0.2,-3.003
3D body: height 0.36, standoff -0.04, extent 0.601,-3.397 1,-3.003
3D body: height 0.36, standoff -0.04, extent 1.401,-3.397 1.8,-3.003
3D body: height 0.36, standoff -0.04, extent -5.799,-3.397 -5.4,-3.003
3D body: height 0.36, standoff -0.04, extent -4.999,-3.397 -4.6,-3.003
3D body: height 0.36, standoff -0.04, extent -4.199,-3.397 -3.8,-3.003
3D body: height 0.36, standoff -0.04, extent -3.399,-3.397 -3,-3.003
3D body: height 0.36, standoff -0.04, extent -2.599,-3.397 -2.2,-3.003
3D body: height 0.36, standoff -0.04, extent 5.401,-2.597 5.8,-2.203
3D body: height 0.36, standoff -0.04, extent 4.601,-2.597 5,-2.203
3D body: height 0.36, standoff -0.04, extent 3.801,-2.597 4.2,-2.203
3D body: height 0.36, standoff -0.04, extent 3.001,-2.597 3.4,-2.203
3D body: height 0.36, standoff -0.04, extent 2.201,-2.597 2.6,-2.203
3D body: height 0.36, standoff -0.04, extent -1.799,-2.597 -1.4,-2.203
3D body: height 0.36, standoff -0.04, extent -0.999,-2.597 -0.6,-2.203
3D body: height 0.36, standoff -0.04, extent -0.199,-2.597 0.2,-2.203
3D body: height 0.36, standoff -0.04, extent 0.601,-2.597 1,-2.203
3D body: height 0.36, standoff -0.04, extent 1.401,-2.597 1.8,-2.203
3D body: height 0.36, standoff -0.04, extent -5.799,-2.597 -5.4,-2.203
3D body: height 0.36, standoff -0.04, extent -4.999,-2.597 -4.6,-2.203
3D body: height 0.36, standoff -0.04, extent -4.199,-2.597 -3.8,-2.203
3D body: height 0.36, standoff -0.04, extent -3.399,-2.597 -3,-2.203
3D body: height 0.36, standoff -0.04, extent -2.599,-2.597 -2.2,-2.203
3D body: height 0.36, standoff -0.04, extent 5.401,-1.797 5.8,-1.403
3D body: height 0.36, standoff -0.04, extent 4.601,-1.797 5,-1.403
3D body: height 0.36, standoff -0.04, extent 3.801,-1.797 4.2,-1.403
3D body: height 0.36, standoff -0.04, extent 3.001,-1.797 3.4,-1.403
3D body: height 0.36, standoff -0.04, extent 2.201,-1.797 2.6,-1.403
3D body: height 0.36, standoff -0.04, extent -1.799,-1.797 -1.4,-1.403
3D body: height 0.36, standoff -0.04, extent -0.999,-1.797 -0.6,-1.403
3D body: height 0.36, standoff -0.04, extent -0.199,-1.797 0.2,-1.403
3D body: height 0.36, standoff -0.04, extent 0.601,-1.797 1,-1.403
3D body: height 0.36, standoff -0.04, extent 1.401,-1.797 1.8,-1.403
3D body: height 0.36, standoff -0.04, extent -5.799,-1.797 -5.4,-1.403
3D body: height 0.36, standoff -0.04, extent -4.999,-1.797 -4.6,-1.403
3D body: height 0.36, standoff -0.04, extent -4.199,-1.797 -3.8,-1.403
3D body: height 0.36, standoff -0.04, extent -3.399,-1.797 -3,-1.403
3D body: height 0.36, standoff -0.04, extent -2.599,-1.797 -2.2,-1.403
3D body: height 0.36, standoff -0.04, extent 5.401,-0.997 5.8,-0.603
3D body: height 0.36, standoff -0.04, extent 4.601,-0.997 5,-0.603
3D body: height 0.36, standoff -0.04, extent 3.801,-0.997 4.2,-0.603
3D body: height 0.36, standoff -0.04, extent 3.001,-0.997 3.4,-0.603
3D body: height 0.36, standoff -0.04, extent 2.201,-0.997 2.6,-0.603
3D body: height 0.36, standoff -0.04, extent -1.799,-0.997 -1.4,-0.603
3D body: height 0.36, standoff -0.04, extent 1.401,-0.997 1.8,-0.603
3D body: height 0.36, standoff -0.04, extent -5.799,-0.997 -5.4,-0.603
3D body: height 0.36, standoff -0.04, extent -4.999,-0.997 -4.6,-0.603
3D body: height 0.36, standoff -0.04, extent -4.199,-0.997 -3.8,-0.603
3D body: height 0.36, standoff -0.04, extent -3.399,-0.997 -3,-0.603
3D body: height 0.36, standoff -0.04, extent -2.599,-0.997 -2.2,-0.603
3D body: height 0.36, standoff -0.04, extent 5.401,-0.197 5.8,0.197
3D body: height 0.36, standoff -0.04, extent 4.601,-0.197 5,0.197
3D body: height 0.36, standoff -0.04, extent 3.801,-0.197 4.2,0.197
3D body: height 0.36, standoff -0.04, extent 3.001,-0.197 3.4,0.197
3D body: height 0.36, standoff -0.04, extent 2.201,-0.197 2.6,0.197
3D body: height 0.36, standoff -0.04, extent -1.799,-0.197 -1.4,0.197
3D body: height 0.36, standoff -0.04, extent 1.401,-0.197 1.8,0.197
3D body: height 0.36, standoff -0.04, extent -5.799,-0.197 -5.4,0.197
3D body: height 0.36, standoff -0.04, extent -4.999,-0.197 -4.6,0.197
3D body: height 0.36, standoff -0.04, extent -4.199,-0.197 -3.8,0.197
3D body: height 0.36, standoff -0.04, extent -3.399,-0.197 -3,0.197
3D body: height 0.36, standoff -0.04, extent -2.599,-0.197 -2.2,0.197
3D body: height 0.36, standoff -0.04, extent 5.401,0.603 5.8,0.997
3D body: height 0.36, standoff -0.04, extent 4.601,0.603 5,0.997
3D body: height 0.36, standoff -0.04, extent 3.801,0.603 4.2,0.997
3D body: height 0.36, standoff -0.04, extent 3.001,0.603 3.4,0.997
3D body: height 0.36, standoff -0.04, extent 2.201,0.603 2.6,0.997
3D body: height 0.36, standoff -0.04, extent -1.799,0.603 -1.4,0.997
3D body: height 0.36, standoff -0.04, extent 1.401,0.603 1.8,0.997
3D body: height 0.36, standoff -0.04, extent -5.799,0.603 -5.4,0.997
3D body: height 0.36, standoff -0.04, extent -4.999,0.603 -4.6,0.997
3D body: height 0.36, standoff -0.04, extent -4.199,0.603 -3.8,0.997
3D body: height 0.36, standoff -0.04, extent -3.399,0.603 -3,0.997
3D body: height 0.36, standoff -0.04, extent -2.599,0.603 -2.2,0.997
3D body: height 0.36, standoff -0.04, extent 5.401,1.403 5.8,1.797
3D body: height 0.36, standoff -0.04, extent 4.601,1.403 5,1.797
3D body: height 0.36, standoff -0.04, extent 3.801,1.403 4.2,1.797
3D body: height 0.36, standoff -0.04, extent 3.001,1.403 3.4,1.797
3D body: height 0.36, standoff -0.04, extent 2.201,1.403 2.6,1.797
3D body: height 0.36, standoff -0.04, extent -1.799,1.403 -1.4,1.797
3D body: height 0.36, standoff -0.04, extent -0.999,1.403 -0.6,1.797
3D body: height 0.36, standoff -0.04, extent -0.199,1.403 0.2,1.797
3D body: height 0.36, standoff -0.04, extent 0.601,1.403 1,1.797
3D body: height 0.36, standoff -0.04, extent 1.401,1.403 1.8,1.797
3D body: height 0.36, standoff -0.04, extent -5.799,1.403 -5.4,1.797
3D body: height 0.36, standoff -0.04, extent -4.999,1.403 -4.6,1.797
3D body: height 0.36, standoff -0.04, extent -4.199,1.403 -3.8,1.797
3D body: height 0.36, standoff -0.04, extent -3.399,1.403 -3,1.797
3D body: height 0.36, standoff -0.04, extent -2.599,1.403 -2.2,1.797
3D body: height 0.36, standoff -0.04, extent 5.401,2.203 5.8,2.597
3D body: height 0.36, standoff -0.04, extent 4.601,2.203 5,2.597
3D body: height 0.36, standoff -0.04, extent 3.801,2.203 4.2,2.597
3D body: height 0.36, standoff -0.04, extent 3.001,2.203 3.4,2.597
3D body: height 0.36, standoff -0.04, extent 2.201,2.203 2.6,2.597
3D body: height 0.36, standoff -0.04, extent -1.799,2.203 -1.4,2.597
3D body: height 0.36, standoff -0.04, extent -0.999,2.203 -0.6,2.597
3D body: height 0.36, standoff -0.04, extent -0.199,2.203 0.2,2.597
3D body: height 0.36, standoff -0.04, extent 0.601,2.203 1,2.597
3D body: height 0.36, standoff -0.04, extent 1.401,2.203 1.8,2.597
3D body: height 0.36, standoff -0.04, extent -5.799,2.203 -5.4,2.597
3D body: height 0.36, standoff -0.04, extent -4.999,2.203 -4.6,2.597
3D body: height 0.36, standoff -0.04, extent -4.199,2.203 -3.8,2.597
3D body: height 0.36, standoff -0.04, extent -3.399,2.203 -3,2.597
3D body: height 0.36, standoff -0.04, extent -2.599,2.203 -2.2,2.597
3D body: height 0.36, standoff -0.04, extent 5.401,3.003 5.8,3.397
3D body: height 0.36, standoff -0.04, extent 4.601,3.003 5,3.397
3D body: height 0.36, standoff -0.04, extent 3.801,3.003 4.2,3.397
3D body: height 0.36, standoff -0.04, extent 3.001,3.003 3.4,3.397
3D body: height 0.36, standoff -0.04, extent 2.201,3.003 2.6,3.397
3D body: height 0.36, standoff -0.04, extent -1.799,3.003 -1.4,3.397
3D body: height 0.36, standoff -0.04, extent -0.999,3.003 -0.6,3.397
3D body: height 0.36, standoff -0.04, extent -0.199,3.003 0.2,3.397
3D body: height 0.36, standoff -0.04, extent 0.601,3.003 1,3.397
3D body: height 0.36, standoff -0.04, extent 1.401,3.003 1.8,3.397
3D body: height 0.36, standoff -0.04, extent -5.799,3.003 -5.4,3.397
3D body: height 0.36, standoff -0.04, extent -4.999,3.003 -4.6,3.397
3D body: height 0.36, standoff -0.04, extent -4.199,3.003 -3.8,3.397
3D body: height 0.36, standoff -0.04, extent -3.399,3.003 -3,3.397
3D body: height 0.36, standoff -0.04, extent -2.599,3.003 -2.2,3.397
3D body: height 0.36, standoff -0.04, extent 5.401,3.803 5.8,4.197
3D body: height 0.36, standoff -0.04, extent 4.601,3.803 5,4.197
3D body: height 0.36, standoff -0.04, extent 3.801,3.803 4.2,4.197
3D body: height 0.36, standoff -0.04, extent 3.001,3.803 3.4,4.197
3D body: height 0.36, standoff -0.04, extent 2.201,3.803 2.6,4.197
3D body: height 0.36, standoff -0.04, extent -1.799,3.803 -1.4,4.197
3D body: height 0.36, standoff -0.04, extent -0.999,3.803 -0.6,4.197
3D body: height 0.36, standoff -0.04, extent -0.199,3.803 0.2,4.197
3D body: height 0.36, standoff -0.04, extent 0.601,3.803 1,4.197
3D body: height 0.36, standoff -0.04, extent 1.401,3.803 1.8,4.197
3D body: height 0.36, standoff -0.04, extent -5.799,3.803 -5.4,4.197
3D body: height 0.36, standoff -0.04, extent -4.999,3.803 -4.6,4.197
3D body: height 0.36, standoff -0.04, extent -4.199,3.803 -3.8,4.197
3D body: height 0.36, standoff -0.04, extent -3.399,3.803 -3,4.197
3D body: height 0.36, standoff -0.04, extent -2.599,3.803 -2.2,4.197
3D body: height 0.36, standoff -0.04, extent 5.401,4.603 5.8,4.997
3D body: height 0.36, standoff -0.04, extent 4.601,4.603 5,4.997
3D body: height 0.36, standoff -0.04, extent 3.801,4.603 4.2,4.997
3D body: height 0.36, standoff -0.04, extent 3.001,4.603 3.4,4.997
3D body: height 0.36, standoff -0.04, extent 2.201,4.603 2.6,4.997
3D body: height 0.36, standoff -0.04, extent -1.799,4.603 -1.4,4.997
3D body: height 0.36, standoff -0.04, extent -0.999,4.603 -0.6,4.997
3D body: height 0.36, standoff -0.04, extent -0.199,4.603 0.2,4.997
3D body: height 0.36, standoff -0.04, extent 0.601,4.603 1,4.997
3D body: height 0.36, standoff -0.04, extent 1.401,4.603 1.8,4.997
3D body: height 0.36, standoff -0.04, extent -5.799,4.603 -5.4,4.997
3D body: height 0.36, standoff -0.04, extent -4.999,4.603 -4.6,4.997
3D body: height 0.36, standoff -0.04, extent -4.199,4.603 -3.8,4.997
3D body: height 0.36, standoff -0.04, extent -3.399,4.603 -3,4.997
3D body: height 0.36, standoff -0.04, extent -2.599,4.603 -2.2,4.997
3D body: height 0.36, standoff -0.04, extent -2.599,5.403 -2.2,5.797
3D body: height 0.36, standoff -0.04, extent -3.399,5.403 -3,5.797
3D body: height 0.36, standoff -0.04, extent -4.199,5.403 -3.8,5.797
3D body: height 0.36, standoff -0.04, extent -4.999,5.403 -4.6,5.797
3D body: height 0.36, standoff -0.04, extent -5.799,5.403 -5.4,5.797
3D body: height 0.36, standoff -0.04, extent 1.401,5.403 1.8,5.797
3D body: height 0.36, standoff -0.04, extent 0.601,5.403 1,5.797
3D body: height 0.36, standoff -0.04, extent -0.199,5.403 0.2,5.797
3D body: height 0.36, standoff -0.04, extent -0.999,5.403 -0.6,5.797
3D body: height 0.36, standoff -0.04, extent -1.799,5.403 -1.4,5.797
3D body: height 0.36, standoff -0.04, extent 2.201,5.403 2.6,5.797
3D body: height 0.36, standoff -0.04, extent 3.001,5.403 3.4,5.797
3D body: height 0.36, standoff -0.04, extent 3.801,5.403 4.2,5.797
3D body: height 0.36, standoff -0.04, extent 4.601,5.403 5,5.797
3D body: height 1.1, standoff 0.3, extent -6.55,-6.55 6.55,6.55
3D body: height 0.36, standoff -0.04, extent 5.401,5.403 5.8,5.797
3D body: height -1.7, standoff -2, extent -2.4,-2 1.6,0
3D body: height -1.7, standoff -2, extent -2.375,0 1.625,2
3D body: height -1.7, standoff -2, extent -10.238,-7.863 -6.238,-5.863
3D body: height -1.7, standoff -2, extent 5.487,-7.863 9.487,-5.863
3D body: height -1.7, standoff -2, extent 5.487,7.862 9.487,9.862
3D body: height -1.7, standoff -2, extent 5.487,5.862 9.487,7.862
3D body: height -1.7, standoff -2, extent 5.487,-9.863 9.487,-7.863
3D body: height -1.7, standoff -2, extent -10.238,-9.863 -6.238,-7.863
3D body: height -1.7, standoff -2, extent -10.238,7.862 -6.238,9.862
3D body: height -1.7, standoff -2, extent -10.238,5.862 -6.238,7.862
3D body "M5398MF.STEP": height -2, standoff -6, extent -10.262,-9.862 9.463,9.863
